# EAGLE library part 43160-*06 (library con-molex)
SDA-43160 Connector Source: http://www.molex.com/pdm_docs/sd/431601306_sd.pdf
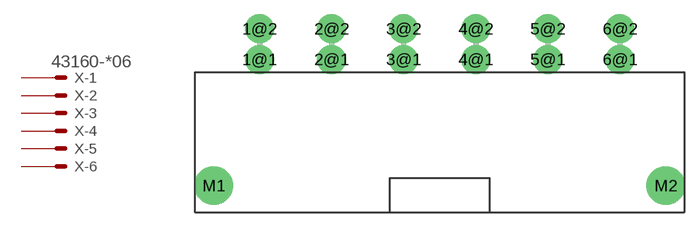
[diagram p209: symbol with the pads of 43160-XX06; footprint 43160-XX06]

Designator prefix X; gates -1=MV2 -2=M2 -3=M2 -4=M2 -5=M2 -6=M2

## 43160-1106 (MF: WALDOM/MOLEX; MPN: 43160-1106; OC_FARNELL: unknown; OC_NEWARK: 54H0259), 43160-1206 (OC_FARNELL: unknown; OC_NEWARK: unknown), 43160-1306 (MPN: 43160-1306; OC_FARNELL: unknown; OC_NEWARK: 92M1484), 43160-1406 (OC_FARNELL: unknown; OC_NEWARK: unknown), 43160-3106 (MF: WALDOM/MOLEX; MPN: 43160-3106; OC_FARNELL: 3293075; OC_NEWARK: 54H0268), 43160-3206 (OC_FARNELL: unknown; OC_NEWARK: unknown), 43160-5106 (MPN: 43160-5106; OC_FARNELL: unknown; OC_NEWARK: 92M1497), 43160-5206 (OC_FARNELL: unknown; OC_NEWARK: unknown), 43160-5306 (MPN: 43160-5306; OC_FARNELL: unknown; OC_NEWARK: 92M1502), 43160-5406 (OC_FARNELL: unknown; OC_NEWARK: unknown), 43160-7306 (MPN: 43160-7306; OC_FARNELL: unknown; OC_NEWARK: 92M1511), 43160-7406 (OC_FARNELL: unknown; OC_NEWARK: unknown)  [43160-XX06]
1@1  -1:S  pas
1@2  -1:S  pas
2@1  -2:S  pas
2@2  -2:S  pas
3@1  -3:S  pas
3@2  -3:S  pas
4@1  -4:S  pas
4@2  -4:S  pas
5@1  -5:S  pas
5@2  -5:S  pas
6@1  -6:S  pas
6@2  -6:S  pas

## Footprint 43160-XX06 (pad centres in mm)
SDA-43160 Connector Source: http://www.molex.com/pdm_docs/sd/431601306_sd.pdf
drill 1.8 pad 3 round: 1@1 -18.725,0; 1@2 -18.725,3.18; 2@1 -11.235,0; 2@2 -11.235,3.18; 3@1 -3.745,0; 3@2 -3.745,3.18; 4@1 3.745,0; 4@2 3.745,3.18; 5@1 11.235,0; 5@2 11.235,3.18; 6@1 18.725,0; 6@2 18.725,3.18
drill 3 pad 3.4 round: M1 -23.475,-13.13; M2 23.475,-13.13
